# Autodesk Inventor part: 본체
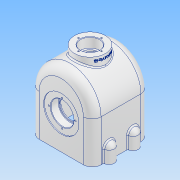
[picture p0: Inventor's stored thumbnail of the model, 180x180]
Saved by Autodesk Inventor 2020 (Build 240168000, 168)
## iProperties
Created: 2023-03
Part Number: 본체
Material: 알루미늄 6061
Document SubType Name: Modeling
Designer: user
Density: 2.7 g/cm^3
Appearance: 알루미늄 - 평지
Mass: 2278.92 g
Surface Area: 1798.49 cm^2
Volume: 844.043 cm^3
Author: user
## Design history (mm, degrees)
sketch "스케치1"
  geometry: L1 (70, -75)-(-70, -75); L2 (-70, -75)-(-70, 19); L3 (-70, 19)-(70, 19); L4 (70, 19)-(70, -75); L5 (70, -75)-(-70, 19); L6 (-70, -75)-(70, 19); A1 r 70 centre (0, 19) between (70, 19) and (-70, 19); 3 further points
  constraints: 12 end point, 4 midpoint, 2 parallel, 2 point on circle, 1 centre point, 1 horizontal, 1 perpendicular, 1 vertical alignment
  dimensions: "d0" = 140 distance of L2.end L3.end; "d1" = 94 distance of L1.end L2.end; "d2" = 75 distance from line of L1 point (0, 0)
extrude "돌출1" new body sketch "스케치1" stored distance "d3" = 130; taper "d4" = 0 deg
fillet "모깎기1" dims "d5" = 20
feature "쉘1" dims "d6" = 10
node "작업 평면1"
sketch "스케치2"
  geometry: C1 r 30 at (0, 0); 1 further point
  constraints: 1 centre point, 1 coincident
  dimensions: "d8" = 60 diameter of C1
extrude "돌출2" join sketch "스케치2" stored distance "d9" = 130; taper "d10" = 45 deg
sketch "스케치3"
  geometry: C1 r 40 at (0, 0); 1 further point
  constraints: 1 centre point, 1 coincident
  dimensions: "d11" = 80 diameter of C1
extrude "돌출3" cut sketch "스케치3" distance "d12" = 2; taper "d13" = 0 deg
sketch "스케치4"
  geometry: C1 r 40 at (0, 0) reference; C2 r 26 at (0, 0)
  constraints: 1 centre point, 1 coincident
  dimensions: "d14" = 52 diameter of C2
extrude "돌출4" cut sketch "스케치4" distance "d15" = 18; taper "d16" = 0 deg
sketch "스케치5"
  geometry: L1 (0, 0)-(0, 30); C1 r 40 at (0, 0) reference; 1 further point
  constraints: 2 end point, 1 coincident, 1 vertical
  dimensions: "d17" = 30 distance of L1.start L1.end
hole "구멍1" sketch "스케치5" at (0, 30) diameter "d18" = 3.242; stored, may be unused: countersink angle "d22" = 90 deg, drill point angle "d24" = 118 deg; dims "d19" = 8, "d20" = 8, "d21" = 4.4, "d23" = 10
sketch "스케치6"
  geometry: C1 r 26 at (0, 0) reference; C2 r 23 at (0, 0)
  constraints: 1 centre point, 1 coincident
  dimensions: "d28" = 46 diameter of C2
extrude "돌출5" cut sketch "스케치6" extent not by distance; stored distance "d29" = 18; taper "d30" = 0 deg
sketch "스케치7"
  geometry: L1 (120, -110)-(120, -20) reference; L2 (120, -26)-(120, -50); L3 (120, -110)-(120, -20) reference; L4 (120, -80)-(120, -104); A1 r 12 centre (120, -38) between (120, -50) and (120, -26); A2 r 12 centre (120, -92) between (120, -104) and (120, -80); 4 further points
  constraints: 7 point on line, 4 end point, 4 point on circle, 2 centre point
  dimensions: "d31" = 24 diameter of A1; "d32" = 24 diameter of A2; "d33" = 54 distance of A2.centre A1.centre; "d34" = 27 vertical distance of point (50, -65) A1.centre (= 0.5 x d33)
extrude "돌출6" join sketch "스케치7" distance "d35" = 40; taper "d36" = 0 deg
fillet "모깎기2" dims "d37" = 12
sketch "스케치8"
  geometry: A1 r 12 centre (120, -92) between (120, -104) and (120, -80) reference; A2 r 12 centre (120, -38) between (120, -50) and (120, -26) reference; A3 r 12 centre (-20, -38) between (-20, -26) and (-20, -50) reference; A4 r 12 centre (-20, -92) between (-20, -80) and (-20, -104) reference; 5 further points
  constraints: 4 coincident
hole "구멍2" sketch "스케치8" at (-20, -38), (120, -92), (120, -38), (-20, -92) diameter "d38" = 10.106; stored, may be unused: countersink angle "d42" = 90 deg, drill point angle "d44" = 118 deg; dims "d39" = 24, "d40" = 8, "d41" = 4.4, "d43" = 26
node "작업 평면2"
sketch "스케치9"
  geometry: C1 r 35 at (-50, -65); 1 further point
  constraints: 1 centre point, 1 coincident
  dimensions: "d46" = 70 diameter of C1
extrude "돌출7" join sketch "스케치9" stored distance "d47" = 40; taper "d48" = 0 deg
sketch "스케치10"
  geometry: C1 r 35 at (0, 0) reference; 2 further points
  constraints: 1 coincident
hole "구멍3" sketch "스케치10" at (0, 0) diameter "d49" = 34; stored, may be unused: countersink angle "d53" = 90 deg, drill point angle "d55" = 0 deg; dims "d50" = 24, "d51" = 43, "d52" = 22, "d54" = 26
sketch "스케치11"
  geometry: L1 (0, 0)-(0, 26); C1 r 35 at (0, 0) reference; 1 further point
  constraints: 2 end point, 1 coincident, 1 vertical
  dimensions: "d56" = 26 distance of L1.start L1.end
hole "구멍4" sketch "스케치11" at (0, 26) diameter "d57" = 3.242; stored, may be unused: countersink angle "d61" = 90 deg, drill point angle "d63" = 118 deg; dims "d58" = 8, "d59" = 43, "d60" = 22, "d62" = 10
fillet "모깎기3" dims "d67" = 1
fillet "모깎기4" dims "d68" = 3
chamfer "모따기1" distance "d69" = 1; stored, may be unused: second distance "d70" = 2, angle "d71" = 45 deg
node "작업 평면3"
sketch "스케치12"
  geometry: L1 (103, -35)-(103, 35) reference; 2 further points
  constraints: 1 horizontal alignment, 1 other
  dimensions: "d73" = 8 distance from line of L1 point (95, 0)
feature "엠보싱1" sketch "스케치12" dims "d0" = 140, "d1" = 94, "d2" = 75, "d74" = 0.5, "d75" = 0
node "솔리드1"
mirror "미러1"
pattern_circular "원형 패턴1" dims angle "d26" = 360 deg
mirror "미러2"
mirror "미러3"
pattern_circular "원형 패턴2" dims angle "d65" = 360 deg
feature "A9D066F2-1C7D-4E18-AEED-F7BC21143FA4" dims "d18" = 3.242, "d19" = 8, "d20" = 8, "d21" = 4.4, "d22" = 90 deg, "d23" = 10, "d24" = 118 deg
other parameters: "d7" = -22, "d45" = -178
